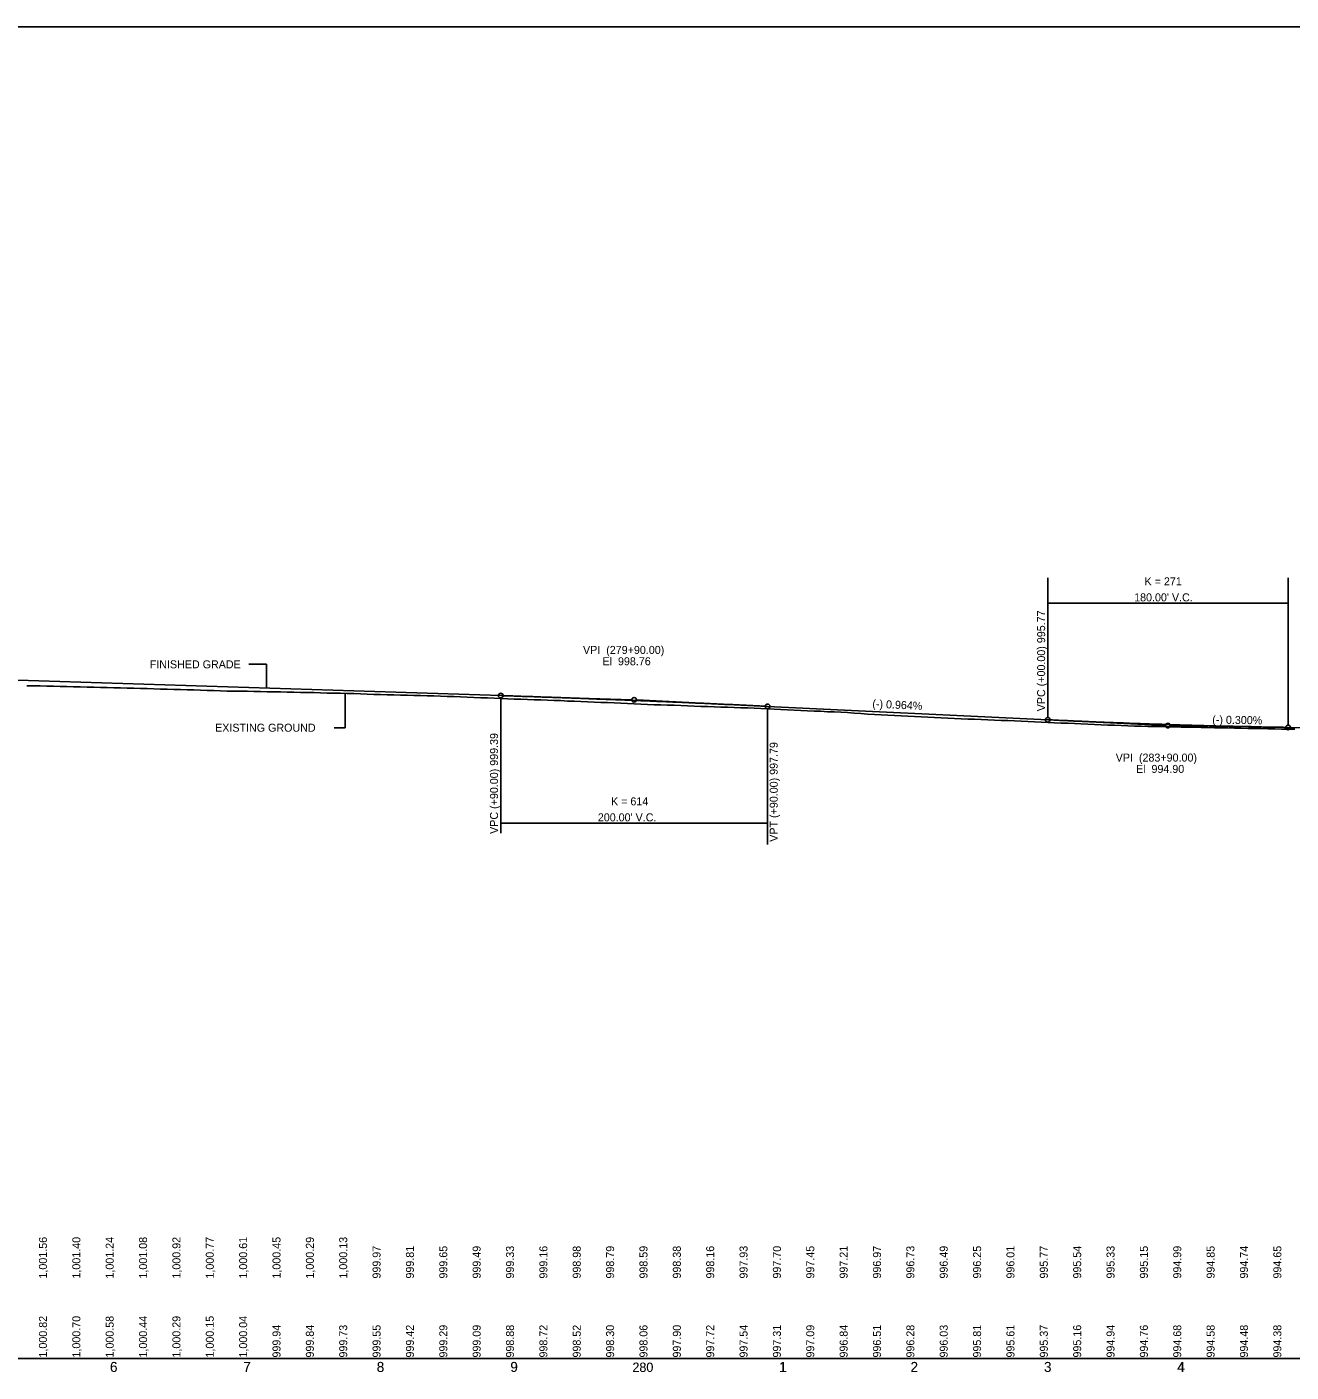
# Model space of a CAD drawing. Extents: x 1608361 to 16979326, y 1092015 to 12565288.
# Drawn here: x 16976521 to 16977468, y 12564278 to 12565286 of the extents above; entities that cross this region are included whole.
import ezdxf

# ---------------------------------------------------------------- set-up
doc = ezdxf.new("R2010")
doc.units = 0
for name, color, linetype in [('CLS_Median', 7, 'Continuous'), ('Default', 7, 'Continuous'), ('points EP', 7, 'Continuous'), ('RD_DDB_EX_Tx', 7, 'Continuous'), ('RD_EX_Fence_ChLk', 7, 'Continuous'), ('RD_EX_H2O', 7, 'Continuous'), ('RD_EX_RW_Approx', 7, 'Continuous'), ('RD_EX_SU_Water', 7, 'Continuous'), ('RD_EX_UT', 7, 'Continuous'), ('RD_HC_TX_Rel_Sta50', 7, 'Continuous'), ('RD_PD_Final_TX', 7, 'Continuous'), ('TEXT2', 7, 'Continuous')]:
    doc.layers.add(name, color=color, linetype=linetype)

msp = doc.modelspace()

# ---------------------------------------------------------------- linework, layer by layer
at = {"layer": 'CLS_Median'}
for p, q in [((16976686.8, 12564808.4), (16976700.2, 12564808.4)), ((16976700.2, 12564808.4), (16976700.2, 12564790.3))]:
    msp.add_line(p, q, dxfattribs=at)
at = {"layer": 'Default'}
msp.add_lwpolyline([(16975985.6, 12564287.8), (16977485.6, 12564287.8), (16977485.6, 12565286), (16975985.6, 12565286)], close=True, dxfattribs=at)
at = {"layer": 'RD_DDB_EX_Tx'}
for p, q in [((16976759, 12564760.7), (16976759, 12564786.5)), ((16976750.8, 12564760.7), (16976759, 12564760.7))]:
    msp.add_line(p, q, dxfattribs=at)
at = {"layer": 'RD_EX_Fence_ChLk'}
for p, q in [((16977285.6, 12564873), (16977285.6, 12564768.4)), ((16977465.6, 12564873), (16977465.6, 12564762.7)), ((16977285.6, 12564854.1), (16977465.6, 12564854.1)), ((16976875.6, 12564681.7), (16976875.6, 12564783)), ((16977075.6, 12564673.2), (16977075.6, 12564775)), ((16976875.6, 12564689.2), (16977075.6, 12564689.2))]:
    msp.add_line(p, q, dxfattribs=at)
for centre in [(16976875.6, 12564784.8), (16977075.6, 12564776.7), (16977285.6, 12564766.6), (16977465.6, 12564760.9)]:
    msp.add_circle(centre, 1.75, dxfattribs=at)
at = {"layer": 'RD_EX_H2O'}
for points in [[(16976520.6, 12564792.1), (16976525.6, 12564792), (16976530.6, 12564792), (16976535.6, 12564791.9), (16976540.6, 12564791.8), (16976545.6, 12564791.7), (16976550.6, 12564791.5), (16976555.6, 12564791.4), (16976560.6, 12564791.3), (16976565.6, 12564791.2), (16976570.6, 12564791), (16976575.6, 12564790.9), (16976580.6, 12564790.8), (16976585.6, 12564790.7), (16976590.6, 12564790.6), (16976595.6, 12564790.4), (16976600.6, 12564790.3), (16976605.6, 12564790.1), (16976610.6, 12564790), (16976615.6, 12564789.8), (16976620.6, 12564789.7), (16976625.6, 12564789.5), (16976630.6, 12564789.4), (16976635.6, 12564789.3), (16976640.6, 12564789.1), (16976645.6, 12564789), (16976650.6, 12564788.8), (16976655.6, 12564788.7), (16976660.6, 12564788.5), (16976665.6, 12564788.4), (16976670.6, 12564788.2), (16976675.6, 12564788.1), (16976680.6, 12564788.1), (16976685.6, 12564788), (16976690.6, 12564787.8), (16976695.6, 12564787.8), (16976700.6, 12564787.7), (16976705.6, 12564787.6), (16976710.6, 12564787.5), (16976715.6, 12564787.4), (16976720.6, 12564787.3), (16976725.6, 12564787.2), (16976730.6, 12564787.1), (16976735.6, 12564787), (16976740.6, 12564786.9), (16976745.6, 12564786.7), (16976750.6, 12564786.6), (16976755.6, 12564786.5), (16976760.6, 12564786.4), (16976765.6, 12564786.3), (16976770.6, 12564786.1), (16976775.6, 12564785.9), (16976780.6, 12564785.7), (16976785.6, 12564785.6), (16976790.6, 12564785.4), (16976795.6, 12564785.3), (16976800.6, 12564785.2), (16976805.6, 12564785), (16976810.6, 12564784.9), (16976815.6, 12564784.8), (16976820.6, 12564784.7), (16976825.6, 12564784.6), (16976830.6, 12564784.4), (16976835.6, 12564784.2), (16976840.6, 12564784), (16976845.6, 12564783.8), (16976850.6, 12564783.6), (16976855.6, 12564783.4), (16976860.6, 12564783.2), (16976865.6, 12564783), (16976870.6, 12564782.9), (16976875.6, 12564782.6), (16976880.6, 12564782.3), (16976885.6, 12564782.2), (16976890.6, 12564782), (16976895.6, 12564781.9), (16976900.6, 12564781.7), (16976905.6, 12564781.6), (16976910.6, 12564781.4), (16976915.6, 12564781.2), (16976920.6, 12564781), (16976925.6, 12564780.7), (16976930.6, 12564780.6), (16976935.6, 12564780.4), (16976940.6, 12564780.2), (16976945.6, 12564779.9), (16976950.6, 12564779.7), (16976955.6, 12564779.5), (16976960.6, 12564779.3), (16976965.6, 12564779.1), (16976970.6, 12564778.8), (16976975.6, 12564778.5), (16976980.6, 12564778.3), (16976985.6, 12564778.1)], [(16976985.6, 12564778.1), (16976990.6, 12564777.9), (16976995.6, 12564777.8), (16977000.6, 12564777.7), (16977005.6, 12564777.5), (16977010.6, 12564777.3), (16977015.6, 12564777.1), (16977020.6, 12564776.9), (16977025.6, 12564776.7), (16977030.6, 12564776.6), (16977035.6, 12564776.4), (16977040.6, 12564776.2), (16977045.6, 12564776), (16977050.6, 12564775.8), (16977055.6, 12564775.6), (16977060.6, 12564775.5), (16977065.6, 12564775.3), (16977070.6, 12564775.1), (16977075.6, 12564774.8), (16977080.6, 12564774.6), (16977085.6, 12564774.3), (16977090.6, 12564774.1), (16977095.6, 12564773.8), (16977100.6, 12564773.6), (16977105.6, 12564773.4), (16977110.6, 12564773.2), (16977115.6, 12564773), (16977120.6, 12564772.7), (16977125.6, 12564772.5), (16977130.6, 12564772.3), (16977135.6, 12564772), (16977140.6, 12564771.6), (16977145.6, 12564771.3), (16977150.6, 12564770.9), (16977155.6, 12564770.6), (16977160.6, 12564770.3), (16977165.6, 12564770.1), (16977170.6, 12564769.9), (16977175.6, 12564769.7), (16977180.6, 12564769.4), (16977185.6, 12564769.2), (16977190.6, 12564768.9), (16977195.6, 12564768.7), (16977200.6, 12564768.4), (16977205.6, 12564768.2), (16977210.6, 12564767.9), (16977215.6, 12564767.7), (16977220.6, 12564767.4), (16977225.6, 12564767.2), (16977230.6, 12564767), (16977235.6, 12564766.8), (16977240.6, 12564766.6), (16977245.6, 12564766.4), (16977250.6, 12564766.2), (16977255.6, 12564766), (16977260.6, 12564765.8), (16977265.6, 12564765.6), (16977270.6, 12564765.4), (16977275.6, 12564765.2), (16977280.6, 12564764.9), (16977285.6, 12564764.7), (16977290.6, 12564764.4), (16977295.6, 12564764.2), (16977300.6, 12564764), (16977305.6, 12564763.8), (16977310.6, 12564763.6), (16977315.6, 12564763.3), (16977320.6, 12564763.1), (16977325.6, 12564762.9), (16977330.6, 12564762.7), (16977335.6, 12564762.5), (16977340.6, 12564762.3), (16977345.6, 12564762.1), (16977350.6, 12564761.9), (16977355.6, 12564761.8), (16977360.6, 12564761.6), (16977365.6, 12564761.5), (16977370.6, 12564761.5), (16977375.6, 12564761.4), (16977380.6, 12564761.3), (16977385.6, 12564761.2), (16977390.6, 12564761.1), (16977395.6, 12564761), (16977400.6, 12564760.9), (16977405.6, 12564760.8), (16977410.6, 12564760.7), (16977415.6, 12564760.6), (16977420.6, 12564760.5), (16977425.6, 12564760.4), (16977430.6, 12564760.3), (16977435.6, 12564760.2), (16977440.6, 12564760.1), (16977445.6, 12564760), (16977450.6, 12564759.9), (16977455.6, 12564759.8), (16977460.6, 12564759.7), (16977465.6, 12564759.6), (16977470.6, 12564759.5)]]:
    msp.add_lwpolyline(points, dxfattribs=at)
at = {"layer": 'RD_EX_RW_Approx'}
for p, q in [((16976885.6, 12564784.4), (16976973.8, 12564781.6)), ((16977065.5, 12564777.2), (16976977.3, 12564781.5)), ((16977285.7, 12564766.6), (16977373.8, 12564762.4)), ((16977465.5, 12564760.9), (16977377.3, 12564762.3))]:
    msp.add_line(p, q, dxfattribs=at)
for centre in [(16976975.6, 12564781.6), (16977375.6, 12564762.3)]:
    msp.add_circle(centre, 1.75, dxfattribs=at)
at = {"layer": 'RD_EX_UT'}
msp.add_line((16972985.6, 12564287.8), (16978789.9, 12564287.8), dxfattribs=at)
at = {"layer": 'RD_HC_TX_Rel_Sta50'}
for p, q in [((16975935.6, 12564814.7), (16976875.6, 12564784.8)), ((16977075.6, 12564776.7), (16977285.6, 12564766.6)), ((16977465.6, 12564760.9), (16977630.6, 12564758.5))]:
    msp.add_line(p, q, dxfattribs=at)
for points in [[(16976875.6, 12564784.8), (16976879.6, 12564784.6), (16976883.6, 12564784.5), (16976887.6, 12564784.4), (16976891.6, 12564784.2), (16976895.6, 12564784.1), (16976899.6, 12564784), (16976903.6, 12564783.8), (16976907.6, 12564783.7), (16976911.6, 12564783.6), (16976915.6, 12564783.4), (16976919.6, 12564783.3), (16976923.6, 12564783.1), (16976927.6, 12564783), (16976931.6, 12564782.8), (16976935.6, 12564782.7), (16976939.6, 12564782.5), (16976943.6, 12564782.4), (16976947.6, 12564782.2), (16976951.6, 12564782.1), (16976955.6, 12564781.9), (16976959.6, 12564781.8), (16976963.6, 12564781.6), (16976967.6, 12564781.5), (16976971.6, 12564781.3), (16976975.6, 12564781.2), (16976979.6, 12564781), (16976983.6, 12564780.8), (16976987.6, 12564780.7), (16976991.6, 12564780.5), (16976995.6, 12564780.3), (16976999.6, 12564780.2), (16977003.6, 12564780), (16977007.6, 12564779.8), (16977011.6, 12564779.7), (16977015.6, 12564779.5), (16977019.6, 12564779.3), (16977023.6, 12564779.1), (16977027.6, 12564779), (16977031.6, 12564778.8), (16977035.6, 12564778.6), (16977039.6, 12564778.4), (16977043.6, 12564778.2), (16977047.6, 12564778.1), (16977051.6, 12564777.9), (16977055.6, 12564777.7), (16977059.6, 12564777.5), (16977063.6, 12564777.3), (16977067.6, 12564777.1), (16977071.6, 12564776.9), (16977075.6, 12564776.7)], [(16977285.6, 12564766.6), (16977289.2, 12564766.5), (16977292.8, 12564766.3), (16977296.4, 12564766.1), (16977300, 12564766), (16977303.6, 12564765.8), (16977307.2, 12564765.6), (16977310.8, 12564765.5), (16977314.4, 12564765.3), (16977318, 12564765.2), (16977321.6, 12564765), (16977325.2, 12564764.9), (16977328.8, 12564764.7), (16977332.4, 12564764.6), (16977336, 12564764.4), (16977339.6, 12564764.3), (16977343.2, 12564764.2), (16977346.8, 12564764), (16977350.4, 12564763.9), (16977354, 12564763.8), (16977357.6, 12564763.6), (16977361.2, 12564763.5), (16977364.8, 12564763.4), (16977368.4, 12564763.3), (16977372, 12564763.2), (16977375.6, 12564763), (16977379.2, 12564762.9), (16977382.8, 12564762.8), (16977386.4, 12564762.7), (16977390, 12564762.6), (16977393.6, 12564762.5), (16977397.2, 12564762.4), (16977400.8, 12564762.3), (16977404.4, 12564762.2), (16977408, 12564762.1), (16977411.6, 12564762), (16977415.2, 12564761.9), (16977418.8, 12564761.8), (16977422.4, 12564761.8), (16977426, 12564761.7), (16977429.6, 12564761.6), (16977433.2, 12564761.5), (16977436.8, 12564761.5), (16977440.4, 12564761.4), (16977444, 12564761.3), (16977447.6, 12564761.2), (16977451.2, 12564761.2), (16977454.8, 12564761.1), (16977458.4, 12564761.1), (16977462, 12564761), (16977465.6, 12564760.9)]]:
    msp.add_spline(points, degree=3, dxfattribs=at)

# ---------------------------------------------------------------- texts
at = {"layer": 'CLS_Median'}
msp.add_text('FINISHED GRADE', height=6, dxfattribs=at).set_placement((16976612.6, 12564805.2))
at = {"layer": 'points EP'}
for s, rotation, p in [('(-) 0.964%', 357.2413, (16977154, 12564775.8)), ('(-) 0.300%', 359.1406, (16977408.8, 12564763.8))]:
    msp.add_text(s, height=6, rotation=rotation, dxfattribs=at).set_placement(p)
at = {"layer": 'RD_DDB_EX_Tx'}
msp.add_text('EXISTING GROUND', height=6, dxfattribs=at).set_placement((16976661.6, 12564757.7))
at = {"layer": 'RD_EX_Fence_ChLk'}
for s, p in [('K = 271', (16977358.1, 12564867.4)), ("180.00' V.C.", (16977350.3, 12564855.4)), ('K = 614', (16976958.3, 12564702.5)), ("200.00' V.C.", (16976948.4, 12564690.5))]:
    msp.add_text(s, height=6, dxfattribs=at).set_placement(p)
for s, p in [('VPC (+00.00) 995.77', (16977283.6, 12564773)), ('VPC (+90.00) 999.39', (16976873.6, 12564681.1)), ('VPT (+90.00) 997.79', (16977083.2, 12564675.2))]:
    msp.add_text(s, height=6, rotation=90, dxfattribs=at).set_placement(p)
at = {"layer": 'RD_EX_RW_Approx'}
for s, p in [('VPI  (279+90.00)', (16976937.3, 12564816)), ('El  998.76', (16976951.9, 12564807.5)), ('VPI  (283+90.00)', (16977336.5, 12564735.3)), ('El  994.90', (16977351.7, 12564726.8))]:
    msp.add_text(s, height=6, dxfattribs=at).set_placement(p)
at = {"layer": 'RD_EX_SU_Water'}
for s, p in [('1,001.56', (16976535.6, 12564347.8)), ('1,001.40', (16976560.6, 12564347.8)), ('1,001.24', (16976585.6, 12564347.8)), ('1,001.08', (16976610.6, 12564347.8)), ('1,000.92', (16976635.6, 12564347.8)), ('1,000.77', (16976660.6, 12564347.8)), ('1,000.61', (16976685.6, 12564347.8)), ('1,000.45', (16976710.6, 12564347.8)), ('1,000.29', (16976735.6, 12564347.8)), ('1,000.13', (16976760.6, 12564347.8)), ('999.97', (16976785.6, 12564347.8)), ('999.81', (16976810.6, 12564347.8)), ('999.65', (16976835.6, 12564347.8)), ('999.49', (16976860.6, 12564347.8)), ('999.33', (16976885.6, 12564347.8)), ('999.16', (16976910.6, 12564347.8)), ('998.98', (16976935.6, 12564347.8)), ('998.79', (16976960.6, 12564347.8)), ('998.59', (16976985.6, 12564347.8)), ('998.38', (16977010.6, 12564347.8)), ('998.16', (16977035.6, 12564347.8)), ('997.93', (16977060.6, 12564347.8)), ('997.70', (16977085.6, 12564347.8)), ('997.45', (16977110.6, 12564347.8)), ('997.21', (16977135.6, 12564347.8)), ('996.97', (16977160.6, 12564347.8)), ('996.73', (16977185.6, 12564347.8)), ('996.49', (16977210.6, 12564347.8)), ('996.25', (16977235.6, 12564347.8)), ('996.01', (16977260.6, 12564347.8)), ('995.77', (16977285.6, 12564347.8)), ('995.54', (16977310.6, 12564347.8)), ('995.33', (16977335.6, 12564347.8)), ('995.15', (16977360.6, 12564347.8)), ('994.99', (16977385.6, 12564347.8)), ('994.85', (16977410.6, 12564347.8)), ('994.74', (16977435.6, 12564347.8)), ('994.65', (16977460.6, 12564347.8))]:
    msp.add_text(s, height=6, rotation=90, dxfattribs=at).set_placement(p)
at = {"layer": 'RD_PD_Final_TX'}
for s, height, p in [('6', 7.5, (16976582.8, 12564277.8)), ('6', 7.5, (16976582.9, 12564277.8)), ('7', 7.5, (16976682.7, 12564277.8)), ('7', 7.5, (16976682.8, 12564277.8)), ('8', 7.5, (16976782.7, 12564277.8)), ('8', 7.5, (16976782.8, 12564277.8)), ('9', 7.5, (16976882.8, 12564277.8)), ('9', 7.5, (16976882.9, 12564277.8)), ('280', 7, (16976974.3, 12564277.8)), ('280', 7, (16976974.4, 12564277.8)), ('1', 7.5, (16977084.2, 12564277.8)), ('1', 7.5, (16977084.6, 12564277.8)), ('2', 7.5, (16977182.7, 12564277.8)), ('2', 7.5, (16977182.8, 12564277.8)), ('3', 7.5, (16977282.7, 12564277.8)), ('3', 7.5, (16977282.8, 12564277.8)), ('4', 7.5, (16977382.5, 12564277.8)), ('4', 7.5, (16977382.8, 12564277.8))]:
    msp.add_text(s, height=height, dxfattribs=at).set_placement(p)
at = {"layer": 'TEXT2'}
for s, p in [('1,000.82', (16976535.6, 12564288.6)), ('1,000.70', (16976560.6, 12564288.6)), ('1,000.58', (16976585.6, 12564288.6)), ('1,000.44', (16976610.6, 12564288.6)), ('1,000.29', (16976635.6, 12564288.6)), ('1,000.15', (16976660.6, 12564288.6)), ('1,000.04', (16976685.6, 12564288.6)), ('999.94', (16976710.6, 12564288.6)), ('999.84', (16976735.6, 12564288.6)), ('999.73', (16976760.6, 12564288.6)), ('999.55', (16976785.6, 12564288.6)), ('999.42', (16976810.6, 12564288.6)), ('999.29', (16976835.6, 12564288.6)), ('999.09', (16976860.6, 12564288.6)), ('998.88', (16976885.6, 12564288.6)), ('998.72', (16976910.6, 12564288.6)), ('998.52', (16976935.6, 12564288.6)), ('998.30', (16976960.6, 12564288.6)), ('998.06', (16976985.6, 12564288.6)), ('997.90', (16977010.6, 12564288.6)), ('997.72', (16977035.6, 12564288.6)), ('997.54', (16977060.6, 12564288.6)), ('997.31', (16977085.6, 12564288.6)), ('997.09', (16977110.6, 12564288.6)), ('996.84', (16977135.6, 12564288.6)), ('996.51', (16977160.6, 12564288.6)), ('996.28', (16977185.6, 12564288.6)), ('996.03', (16977210.6, 12564288.6)), ('995.81', (16977235.6, 12564288.6)), ('995.61', (16977260.6, 12564288.6)), ('995.37', (16977285.6, 12564288.6)), ('995.16', (16977310.6, 12564288.6)), ('994.94', (16977335.6, 12564288.6)), ('994.76', (16977360.6, 12564288.6)), ('994.68', (16977385.6, 12564288.6)), ('994.58', (16977410.6, 12564288.6)), ('994.48', (16977435.6, 12564288.6)), ('994.38', (16977460.6, 12564288.6))]:
    msp.add_text(s, height=6, rotation=90, dxfattribs=at).set_placement(p)

doc.saveas('drawing.dxf')
